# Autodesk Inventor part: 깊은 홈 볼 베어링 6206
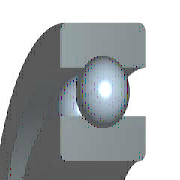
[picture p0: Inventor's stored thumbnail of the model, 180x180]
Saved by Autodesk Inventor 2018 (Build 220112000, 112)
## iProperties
IsCustomPart: 1
Created: 2012-02
Part Number: 깊은 홈 볼 베어링 6206
Material: 강철, 연강
Description: 깊은 그루부 볼 베어링
Document SubType Name: Modeling
Standard: JIS B 1521
Designer: mdu-01
Standards Organization: JIS
Language: ko-KR
Size Designation: 6206 30x62x16
Categories: <MemberInstance><Categories><Category DisplayName="샤프트 부품" InternalName="7f7aeb1f-a693-4053-b835-cee3144e0d98" Mnemonic="SHFT"><Category DisplayName="베어링" Inter
Density: 1 g/cm^3
Appearance: 강철(1)
Author: mdu-01
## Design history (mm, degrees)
sketch "스케치" dims "d0" = 8.32 (= -0.26 x WD + 0.26 x BD)
  geometry: L1 (3.84, 23)-(12.16, 23); L2 (8, 23)-(8, 18.84); L3 (8, 23)-(8, 27.16); L4 (4.909, 20.216)-(0, 20.216); L5 (0, 15)-(16, 15); L6 (4.909, 25.784)-(0, 25.784); L7 (0, 31)-(16, 31); L8 (16, 15)-(16, 20.216); L9 (11.091, 20.216)-(16, 20.216); L10 (11.091, 25.784)-(16, 25.784); L11 (16, 31)-(16, 25.784); L12 (-1.4, 0)-(8.4, 0) reference; L13 (0, -0.3)-(0, 5.3) reference
  constraints: 22 end point, 4 point on line, 2 collinear, 2 perpendicular, 2 symmetric about line, 1 midpoint, 1 parallel, 14 other
  dimensions: "d9" = 30 diameter of L5 L12 (= WD); "d11" = 62 diameter of L7 L12 (= BD); "d12" = 16 distance between parallel lines of L8 L13 (= KB); "d13" = 40.432 diameter of L9 L12 (= 0.326 x BD + 0.674 x WD)
revolve "본체" stored, may be unused: angle "d6" = 90 deg
revolve "볼" stored, may be unused: angle "d7" = 90 deg
pattern_circular "IDS_ARRAYBALL[SIMPL:T]" dims angle "d3" = 360 deg
body "Solid1"
fillet "모깎기1" dims "d1" = 1 (= KRS)
other parameters: "WD" = 30 [user parameter; used in 5 equation terms], "BD" = 62 [user parameter; used in 5 equation terms], "KB" = 16 [user parameter; used in 1 equation term], "KRS" = 1 [user parameter; used in 1 equation term], "d4" = 0, "d5" = 0, "d8" = 0, "d14" = 0, "d15" = 0, "BBA" = 0 [user parameter], "BC0" = 1.12e+07 [user parameter], "BC" = 1.95e+07 [user parameter], "BR" = 31 (= 0.5 x BD) [user parameter], "WR" = 15 (= 0.5 x WD) [user parameter]
